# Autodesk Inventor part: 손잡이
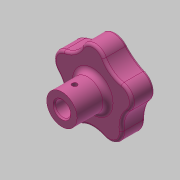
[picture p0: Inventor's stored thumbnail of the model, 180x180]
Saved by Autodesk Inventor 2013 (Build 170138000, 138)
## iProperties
Created: 2020-03
Part Number: 손잡이
Material: 알루미늄 6061
Document SubType Name: Modeling
Designer: mduedu
Density: 1 g/cm^3
Author: mduedu
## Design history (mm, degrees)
sketch "스케치1" dims "d1" = 22
  geometry: C1 r 16 at (0, 0); C2 r 5 at (0, 11); C3 r 5 at (-10.462, 3.399); C4 r 5 at (-6.466, -8.899); C5 r 5 at (6.466, -8.899); C6 r 5 at (10.462, 3.399); 2 further points
  constraints: 6 centre point, 2 coincident, 2 vertical alignment, 1 tangent, 13 other
  dimensions: "d0" = 32 diameter of C1; "d4" = 360 deg dimension on point (0, 0) C2.centre (derived); "d6" = 10 diameter of C2 (derived)
extrude "돌출1" new body sketch "스케치1" distance "d8" = 10; taper "d9" = 0 deg
fillet "모깎기1" dims "d10" = 10
fillet "모깎기2" dims "d11" = 10
fillet "모깎기3" dims "d12" = 10
fillet "모깎기4" dims "d13" = 10
fillet "모깎기5" dims "d14" = 10
sketch "스케치2"
  geometry: L1 (16, 10)-(16, 0) reference; L2 (16, 0)-(-12.434, 0) reference; L3 (-12.434, 0)-(-12.434, 10) reference; L4 (-12.434, 10)-(16, 10) reference; L5 (10.5, 0)-(16, 1.169); L6 (16, 1.169)-(16, 0); L7 (16, 0)-(10.5, 0); L8 (0, 0)-(0, 10)
  constraints: 8 end point, 3 perpendicular, 3 point on line
  dimensions: "d15" = 5.5 distance of L5.start L1.end; "d16" = 12 deg angle of L2 L5
revolve "회전1" sketch "스케치2" stored, may be unused: angle "d17" = 90 deg
fillet "모깎기6" dims "d18" = 1
sketch "스케치3"
  geometry: C1 r 6 at (0, 0); 1 further point
  constraints: 1 centre point, 1 coincident
  dimensions: "d19" = 12 diameter of C1
extrude "돌출2" join sketch "스케치3" distance "d20" = 12.2; taper "d21" = 0 deg
fillet "모깎기7" dims "d22" = 2
hole "구멍1" diameter "d25" = 6; stored, may be unused: countersink angle "d29" = 90 deg, drill point angle "d31" = 118 deg; dims "d23" = 10, "d24" = 10, "d26" = 6, "d27" = 4, "d28" = 2, "d30" = 15
sketch "스케치4"
  geometry: L1 (6, 22.2)-(-6, 22.2) reference; C1 r 1 at (0, 17.2); 1 further point
  constraints: 1 centre point, 1 vertical alignment
  dimensions: "d32" = 2 diameter of C1; "d34" = 5 distance from line of C1.centre L1
extrude "돌출3" cut sketch "스케치4" stored distance "d35" = 12.2; taper "d36" = 0 deg
chamfer "모따기2" distance "d40" = 0.5; stored, may be unused: second distance "d41" = 2, angle "d42" = 45 deg
node "솔리드1"
node "절단 모서리 투영1"
